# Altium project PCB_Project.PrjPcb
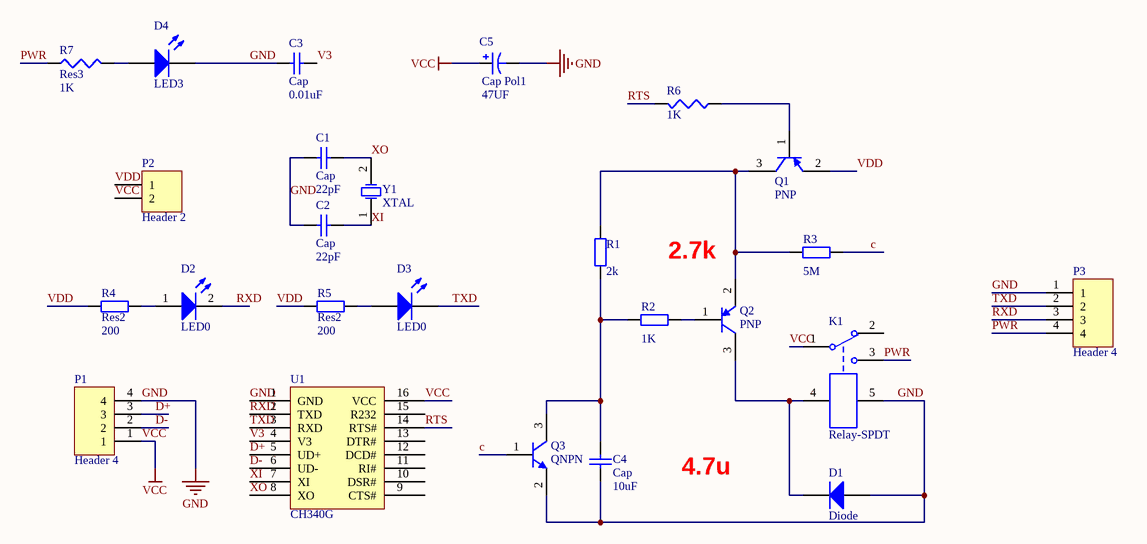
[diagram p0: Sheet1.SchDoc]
1 sheet, 25 parts. Net scope: global (net labels, ports and power ports of the same name join across sheets).
Board file: PCB2.PcbDoc

## Sheet Sheet1.SchDoc
size A4

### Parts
C1  Cap  value 22pF  [0805]
C2  Cap  value 22pF  [0805]
C3  Cap  value 0.01uF  [0805]
C4  Cap  value 10uF  [0805]
C5  Cap Pol1  value 47UF  [0805_RES]
D1  Diode  [1206]
D2  LED0  [LED_3MM]
D3  LED0  [LED_3MM]
D4  LED3  [0805]
K1  Relay-SPDT  [Relay5V]
P1  Header 4  [USB_2]
P2  Header 2  [HDR1X2]
P3  Header 4  [SIP4]
Q1  PNP  [SOT-23B_N]
Q2  PNP  [SOT-23B_N]
Q3  QNPN  [SOT-23B_N]
R1  value 2k  [0805]  (hidden comment: Res2)
R2  value 1K  [0805]  (hidden comment: Res2)
R3  value 5M  [0805]  (hidden comment: Res0)
R4  Res2  value 200  [0805]
R5  Res2  value 200  [0805]
R6  value 1K  [0805_RES]  (hidden comment: Res3)
R7  Res3  value 1K  [J1-0603]
U1  CH340G  [SOP16]
Y1  XTAL  [XTAL]

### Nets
GND: C1.2 C2.1 C3.1 C4.1 C5.2 D1.1(A) D4.2(K) K1.5 P1.4 P3.1 Q3.2(E) U1.1(GND)
VCC: C5.1 K1.1 P1.1 P2.2 U1.16(VCC)
c: Q3.1(B) R3.1
D+: P1.3 U1.5(UD+)
D-: P1.2 U1.6(UD-)
PWR: K1.3 P3.4 R7.1
RTS: R6.2 U1.14(RTS#)
RXD: D2.2(K) P3.3 U1.2(TXD)
TXD: D3.2(K) P3.2 U1.3(RXD)
V3: C3.2 U1.4(V3)
VDD: P2.1 Q1.2(E) R4.2 R5.2
XI: C2.2 U1.7(XI) Y1.1(OSC1)
XO: C1.1 U1.8(XO) Y1.2(OSC2)
NetC4_2: C4.2 Q3.3(C) R1.1 R2.2
NetD1_2: D1.2(K) K1.4 Q2.3(C)
NetD2_1: D2.1(A) R4.1
NetD3_1: D3.1(A) R5.1
NetD4_1: D4.1(A) R7.2
NetQ1_1: Q1.1(B) R6.1
NetQ1_3: Q1.3(C) Q2.2(E) R1.2 R3.2
NetQ2_1: Q2.1(B) R2.1

Not connected (* = marked no-connect by the designer): K1 2; U1 9(CTS#) 10(DSR#) 11(RI#) 12(DCD#) 13(DTR#) 15(R232)

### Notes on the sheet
- (near R1) 2.7k
- (near C4) 4.7u

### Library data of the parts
C1-C4 = Cap: Capacitor
C5 = Cap Pol1: Polarized Capacitor (Radial)
D1 = Diode: Default Diode
D2 D3 = LED0: Typical INFRARED GaAs LED
D4 = LED3: Typical BLUE SiC LED
K1 = Relay-SPDT: Single-Pole Dual-Throw Relay
P1 P3 = Header 4: Header, 4-Pin
P2 = Header 2: Header, 2-Pin
Q1 Q2 = PNP: PNP Bipolar Transistor
Q3 = QNPN: NPN Bipolar Transistor
R1-R5 = Res2: Resistor
R6 R7 = Res3: Resistor
Y1 = XTAL: Crystal Oscillator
